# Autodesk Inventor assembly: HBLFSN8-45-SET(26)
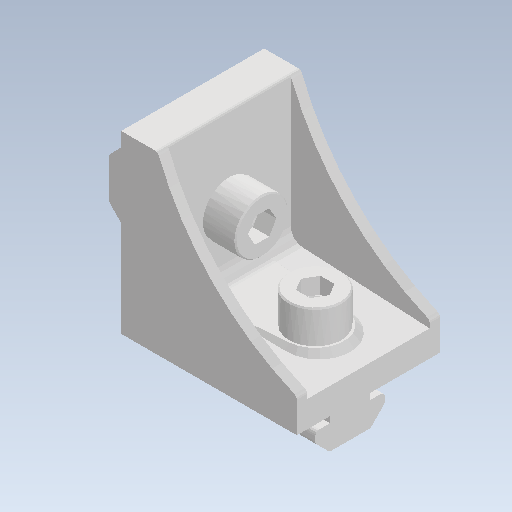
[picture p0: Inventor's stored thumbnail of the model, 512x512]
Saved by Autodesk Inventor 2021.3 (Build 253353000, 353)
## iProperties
Created: 2022-02
Part Number: HBLFSN8-45-SET(26)
Document SubType Name: Assembly
Designer: kengo
Author: kengo
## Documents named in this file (4)
- C:\Users\kengo\Documents\S2S_frame\SDC345\frame_misumi_ver12\HBLFSN8-45-SET(26).iam
- C:\Users\kengo\Documents\S2S_frame\SDC345\frame_misumi_ver12\HBLFSN8-45.ipt
- C:\Users\kengo\Documents\S2S_frame\SDC345\frame_misumi_ver12\HNTT8-8.ipt
- C:\Users\kengo\Documents\S2S_frame\SDC345\frame_misumi_ver12\CBM8-20.ipt
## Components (5 placed, 3 different names)
1. HBLFSN8-45
2. HNTT8-8
3. CBM8-20
4. HNTT8-8:1
5. CBM8-20:1
